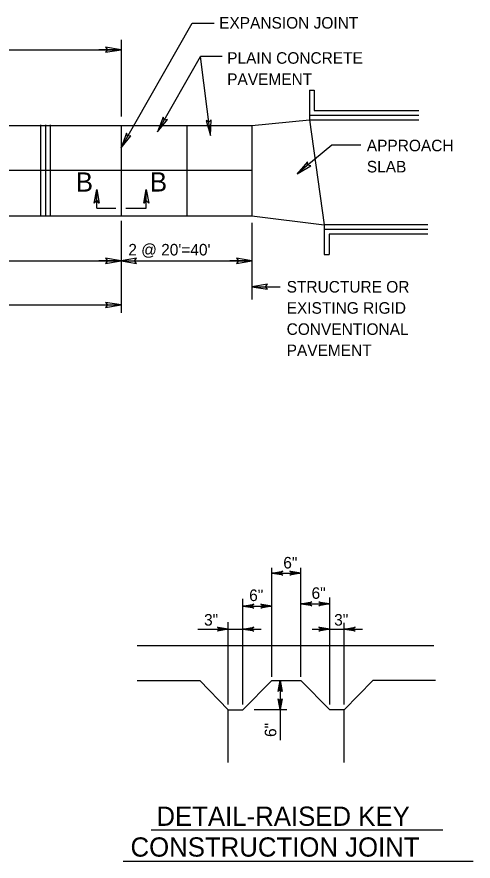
# Model space of a CAD drawing. Extents: x 3.1 to 10.2, y 1.2 to 11.3.
# Drawn here: x 6.918 to 9.286, y 6.773 to 11.16 of the extents above; entities that cross this region are included whole.
import ezdxf

# ---------------------------------------------------------------- set-up
doc = ezdxf.new("R2010")
doc.units = 0
for name, color, linetype in [('DETL-DIMS', 7, 'Continuous'), ('DETL-LINE', 7, 'Continuous'), ('DETL-NOTE', 7, 'Continuous'), ('DETL-TITL', 7, 'Continuous')]:
    doc.layers.add(name, color=color, linetype=linetype)

msp = doc.modelspace()

# ---------------------------------------------------------------- linework, layer by layer
at = {"layer": 'DETL-DIMS'}
for p, q in [((7.4583, 11.0402), (7.4583, 10.6414)), ((5.4958, 10.9893), (7.4583, 10.9893)), ((7.4583, 10.9893), (7.3436, 10.9893)), ((7.4583, 10.9893), (7.3785, 11.0026)), ((7.3785, 11.0026), (7.3886, 10.9893)), ((7.4583, 10.9893), (7.3785, 11.0026)), ((7.3785, 11.0026), (7.3886, 10.9893)), ((7.3886, 10.9893), (7.3786, 10.976)), ((7.3786, 10.976), (7.4583, 10.9893)), ((7.3886, 10.9893), (7.3786, 10.976)), ((7.3786, 10.976), (7.4583, 10.9893)), ((7.6486, 10.5634), (7.8712, 10.9542)), ((7.983, 10.9542), (7.8712, 10.9542)), ((7.9234, 10.5437), (7.8712, 10.9542)), ((7.6765, 10.6393), (7.6486, 10.5634)), ((7.6765, 10.6393), (7.6486, 10.5634)), ((7.6486, 10.5634), (7.6996, 10.6262)), ((7.6486, 10.5634), (7.6996, 10.6262)), ((7.6831, 10.624), (7.6765, 10.6393)), ((7.6831, 10.624), (7.6765, 10.6393)), ((7.6996, 10.6262), (7.6831, 10.624)), ((7.6996, 10.6262), (7.6831, 10.624)), ((7.9146, 10.6129), (7.9, 10.6212)), ((7.9, 10.6212), (7.9234, 10.5437)), ((7.9146, 10.6129), (7.9, 10.6212)), ((7.9, 10.6212), (7.9234, 10.5437)), ((7.9264, 10.6246), (7.9146, 10.6129)), ((7.9264, 10.6246), (7.9146, 10.6129)), ((7.9234, 10.5437), (7.9264, 10.6246)), ((7.9234, 10.5437), (7.9264, 10.6246)), ((7.4862, 10.5549), (7.4583, 10.479)), ((7.4862, 10.5549), (7.4583, 10.479)), ((7.4583, 10.479), (7.5093, 10.5418)), ((7.4583, 10.479), (7.5093, 10.5418)), ((7.4928, 10.5396), (7.4862, 10.5549)), ((7.4928, 10.5396), (7.4862, 10.5549)), ((7.5093, 10.5418), (7.4928, 10.5396)), ((7.5093, 10.5418), (7.4928, 10.5396)), ((8.4261, 10.4058), (8.3734, 10.3444)), ((8.4261, 10.4058), (8.3734, 10.3444)), ((8.427, 10.3891), (8.4261, 10.4058)), ((8.427, 10.3891), (8.4261, 10.4058)), ((8.3734, 10.3444), (8.4432, 10.3854)), ((8.3734, 10.3444), (8.4432, 10.3854)), ((8.4432, 10.3854), (8.427, 10.3891)), ((8.4432, 10.3854), (8.427, 10.3891)), ((7.3323, 10.2636), (7.3197, 10.1921)), ((7.3323, 10.1661), (7.3323, 10.2636)), ((7.3323, 10.2636), (7.3449, 10.1921)), ((7.5894, 10.2636), (7.5768, 10.1921)), ((7.5894, 10.1661), (7.5894, 10.2636)), ((7.5894, 10.2636), (7.602, 10.1921)), ((7.3197, 10.1921), (7.3323, 10.2056)), ((7.3323, 10.2056), (7.3449, 10.1921)), ((7.5768, 10.1921), (7.5894, 10.2056)), ((7.5894, 10.2056), (7.602, 10.1921)), ((7.3323, 10.1661), (7.431, 10.1661)), ((7.4827, 10.1661), (7.5894, 10.1661)), ((7.4583, 10.1008), (7.4583, 9.6211)), ((8.1382, 10.0903), (8.1382, 9.692)), ((5.7252, 9.8922), (7.4583, 9.8922)), ((7.4583, 9.8922), (7.3436, 9.8922)), ((7.4583, 9.8922), (7.3785, 9.9055)), ((7.3785, 9.9055), (7.3886, 9.8922)), ((7.4583, 9.8922), (7.3785, 9.9055)), ((7.3785, 9.9055), (7.3886, 9.8922)), ((7.3886, 9.8922), (7.3786, 9.8788)), ((7.3786, 9.8788), (7.4583, 9.8922)), ((7.3886, 9.8922), (7.3786, 9.8788)), ((7.3786, 9.8788), (7.4583, 9.8922)), ((7.5381, 9.9056), (7.4583, 9.8922)), ((7.5381, 9.9056), (7.4583, 9.8922)), ((7.4583, 9.8922), (8.1382, 9.8922)), ((7.4583, 9.8922), (7.5381, 9.879)), ((7.4583, 9.8922), (7.5381, 9.879)), ((7.4583, 9.8922), (7.605, 9.8922)), ((7.5281, 9.8922), (7.5381, 9.9056)), ((7.5281, 9.8922), (7.5381, 9.9056)), ((7.5381, 9.879), (7.5281, 9.8922)), ((7.5381, 9.879), (7.5281, 9.8922)), ((8.1382, 9.8922), (8.0235, 9.8922)), ((8.1382, 9.8922), (8.0584, 9.9055)), ((8.0584, 9.9055), (8.0685, 9.8922)), ((8.1382, 9.8922), (8.0584, 9.9055)), ((8.0584, 9.9055), (8.0685, 9.8922)), ((8.0685, 9.8922), (8.0585, 9.8788)), ((8.0585, 9.8788), (8.1382, 9.8922)), ((8.0685, 9.8922), (8.0585, 9.8788)), ((8.0585, 9.8788), (8.1382, 9.8922)), ((8.218, 9.7711), (8.1382, 9.7577)), ((8.218, 9.7711), (8.1382, 9.7577)), ((8.1382, 9.7577), (8.218, 9.7445)), ((8.1382, 9.7577), (8.218, 9.7445)), ((8.1382, 9.7577), (8.2849, 9.7577)), ((8.208, 9.7577), (8.218, 9.7711)), ((8.208, 9.7577), (8.218, 9.7711)), ((8.218, 9.7445), (8.208, 9.7577)), ((8.218, 9.7445), (8.208, 9.7577)), ((5.4958, 9.6628), (7.4583, 9.6628)), ((7.4583, 9.6628), (7.3785, 9.6761)), ((7.3785, 9.6761), (7.3886, 9.6628)), ((7.4583, 9.6628), (7.3785, 9.6761)), ((7.3785, 9.6761), (7.3886, 9.6628)), ((7.3886, 9.6628), (7.3786, 9.6494)), ((7.3786, 9.6494), (7.4583, 9.6628)), ((7.3886, 9.6628), (7.3786, 9.6494)), ((7.3786, 9.6494), (7.4583, 9.6628)), ((8.2412, 7.7307), (8.2412, 8.2962)), ((8.3918, 7.7307), (8.3918, 8.2962)), ((8.2412, 8.2693), (8.3918, 8.2693)), ((8.0908, 7.586), (8.0908, 8.1362)), ((8.5422, 7.586), (8.5422, 8.1419)), ((8.0908, 8.0982), (8.2412, 8.0982)), ((8.3918, 8.1096), (8.5422, 8.1096)), ((8.0155, 7.586), (8.0155, 8.0144)), ((8.6174, 7.586), (8.6174, 8.0106)), ((7.858, 7.9782), (8.1855, 7.9782)), ((8.4502, 7.9782), (8.7122, 7.9782)), ((8.2841, 7.7106), (8.2841, 7.4013)), ((8.1494, 7.56), (8.3188, 7.56))]:
    msp.add_line(p, q, dxfattribs=at)
for points in [[(7.4583, 10.479), (7.8275, 11.1271), (7.9422, 11.1271)], [(8.7036, 10.4935), (8.552, 10.4935), (8.3734, 10.3444)], [(8.2412, 8.2693), (8.2977, 8.2799), (8.2933, 8.2768), (8.2911, 8.2731), (8.2904, 8.2693), (8.2911, 8.2655), (8.2933, 8.2617), (8.2977, 8.2587), (8.2412, 8.2693), (8.2933, 8.2617), (8.2911, 8.2655), (8.2412, 8.2693), (8.2904, 8.2693), (8.2911, 8.2731), (8.2412, 8.2693), (8.2933, 8.2768)], [(8.3918, 8.2693), (8.3353, 8.2587), (8.3396, 8.2617), (8.3419, 8.2655), (8.3425, 8.2693), (8.3419, 8.2731), (8.3396, 8.2768), (8.3353, 8.2799), (8.3918, 8.2693), (8.3396, 8.2768), (8.3419, 8.2731), (8.3918, 8.2693), (8.3425, 8.2693), (8.3419, 8.2655), (8.3918, 8.2693), (8.3396, 8.2617)], [(8.3918, 8.1096), (8.4482, 8.1202), (8.4439, 8.1172), (8.4416, 8.1134), (8.441, 8.1096), (8.4416, 8.1058), (8.4439, 8.102), (8.4482, 8.099), (8.3918, 8.1096), (8.4439, 8.102), (8.4416, 8.1058), (8.3918, 8.1096), (8.441, 8.1096), (8.4416, 8.1134), (8.3918, 8.1096), (8.4439, 8.1172)], [(8.5422, 8.1096), (8.4857, 8.099), (8.49, 8.102), (8.4923, 8.1058), (8.4929, 8.1096), (8.4923, 8.1134), (8.49, 8.1172), (8.4857, 8.1202), (8.5422, 8.1096), (8.49, 8.1172), (8.4923, 8.1134), (8.5422, 8.1096), (8.4929, 8.1096), (8.4923, 8.1058), (8.5422, 8.1096), (8.49, 8.102)], [(8.0908, 8.0982), (8.1473, 8.1087), (8.1429, 8.1057), (8.1407, 8.1019), (8.14, 8.0982), (8.1407, 8.0944), (8.1429, 8.0906), (8.1473, 8.0876), (8.0908, 8.0982), (8.1429, 8.0906), (8.1407, 8.0944), (8.0908, 8.0982), (8.14, 8.0982), (8.1407, 8.1019), (8.0908, 8.0982), (8.1429, 8.1057)], [(8.2412, 8.0982), (8.1847, 8.0876), (8.189, 8.0906), (8.1913, 8.0944), (8.1919, 8.0982), (8.1913, 8.1019), (8.189, 8.1057), (8.1847, 8.1087), (8.2412, 8.0982), (8.189, 8.1057), (8.1913, 8.1019), (8.2412, 8.0982), (8.1919, 8.0982), (8.1913, 8.0944), (8.2412, 8.0982), (8.189, 8.0906)], [(8.0155, 7.9782), (7.959, 7.9676), (7.9633, 7.9706), (7.9656, 7.9744), (7.9662, 7.9782), (7.9656, 7.982), (7.9633, 7.9858), (7.959, 7.9888), (8.0155, 7.9782), (7.9633, 7.9858), (7.9656, 7.982), (8.0155, 7.9782), (7.9662, 7.9782), (7.9656, 7.9744), (8.0155, 7.9782), (7.9633, 7.9706)], [(8.0908, 7.9782), (8.1473, 7.9888), (8.1429, 7.9858), (8.1407, 7.982), (8.14, 7.9782), (8.1407, 7.9744), (8.1429, 7.9706), (8.1473, 7.9676), (8.0908, 7.9782), (8.1429, 7.9706), (8.1407, 7.9744), (8.0908, 7.9782), (8.14, 7.9782), (8.1407, 7.982), (8.0908, 7.9782), (8.1429, 7.9858)], [(8.5422, 7.9782), (8.4857, 7.9676), (8.49, 7.9706), (8.4923, 7.9744), (8.4929, 7.9782), (8.4923, 7.982), (8.49, 7.9858), (8.4857, 7.9888), (8.5422, 7.9782), (8.49, 7.9858), (8.4923, 7.982), (8.5422, 7.9782), (8.4929, 7.9782), (8.4923, 7.9744), (8.5422, 7.9782), (8.49, 7.9706)], [(8.6174, 7.9782), (8.6739, 7.9888), (8.6696, 7.9858), (8.6673, 7.982), (8.6667, 7.9782), (8.6673, 7.9744), (8.6696, 7.9706), (8.6739, 7.9676), (8.6174, 7.9782), (8.6696, 7.9706), (8.6673, 7.9744), (8.6174, 7.9782), (8.6667, 7.9782), (8.6673, 7.982), (8.6174, 7.9782), (8.6696, 7.9858)], [(8.2841, 7.7106), (8.2947, 7.6541), (8.2917, 7.6584), (8.2879, 7.6607), (8.2841, 7.6613), (8.2803, 7.6607), (8.2765, 7.6584), (8.2735, 7.6541), (8.2841, 7.7106), (8.2765, 7.6584), (8.2803, 7.6607), (8.2841, 7.7106), (8.2841, 7.6613), (8.2879, 7.6607), (8.2841, 7.7106), (8.2917, 7.6584)], [(8.2841, 7.56), (8.2735, 7.6165), (8.2765, 7.6122), (8.2803, 7.6099), (8.2841, 7.6093), (8.2879, 7.6099), (8.2917, 7.6122), (8.2947, 7.6165), (8.2841, 7.56), (8.2917, 7.6122), (8.2879, 7.6099), (8.2841, 7.56), (8.2841, 7.6093), (8.2803, 7.6099), (8.2841, 7.56), (8.2765, 7.6122)]]:
    msp.add_lwpolyline(points, dxfattribs=at)
for points in [[(7.3197, 10.1921), (7.3323, 10.2636), (7.3449, 10.1921), (7.3323, 10.2056)], [(7.5768, 10.1921), (7.5894, 10.2636), (7.602, 10.1921), (7.5894, 10.2056)]]:
    msp.add_lwpolyline(points, close=True, dxfattribs=at)
at = {"layer": 'DETL-LINE'}
for p, q in [((8.4365, 10.7786), (8.4615, 10.7786)), ((8.4615, 10.7786), (8.4615, 10.6742)), ((8.4615, 10.6742), (9.0037, 10.6742)), ((8.1382, 10.595), (8.4365, 10.6242)), ((8.4365, 10.6492), (9.0037, 10.6492)), ((8.4365, 10.6242), (8.5136, 10.0799)), ((4.9869, 10.595), (8.1382, 10.595)), ((7.0408, 10.5982), (7.0408, 10.1289)), ((7.0658, 10.5982), (7.0658, 10.1289)), ((7.0908, 10.5982), (7.0908, 10.1289)), ((7.4583, 10.595), (7.4583, 10.1258)), ((7.8004, 10.595), (7.8004, 10.1258)), ((8.1382, 10.595), (8.1382, 10.1258)), ((4.9869, 10.3635), (8.1382, 10.3635)), ((4.9869, 10.1258), (8.1382, 10.1258)), ((8.1382, 10.1258), (8.5136, 10.0799)), ((9.0517, 10.0799), (8.5136, 10.0799)), ((8.5136, 10.0799), (8.5136, 9.9256)), ((9.0517, 10.0549), (8.5136, 10.0549)), ((9.0517, 10.0299), (8.5386, 10.0299)), ((8.5386, 10.0299), (8.5386, 9.9256)), ((8.5136, 9.9256), (8.5386, 9.9256)), ((7.5422, 7.893), (9.0819, 7.893)), ((7.5422, 7.7106), (7.8667, 7.7106)), ((7.8667, 7.7106), (8.0155, 7.5588)), ((8.2412, 7.7106), (8.0908, 7.5588)), ((8.2412, 7.7106), (8.3918, 7.7106)), ((8.3918, 7.7106), (8.5422, 7.5588)), ((8.7662, 7.7106), (8.6174, 7.5588)), ((9.0907, 7.7106), (8.7662, 7.7106)), ((8.0155, 7.5588), (8.0908, 7.5588)), ((8.0155, 7.2845), (8.0155, 7.5588)), ((8.6174, 7.5588), (8.5422, 7.5588)), ((8.6174, 7.2845), (8.6174, 7.5588))]:
    msp.add_line(p, q, dxfattribs=at)
msp.add_lwpolyline([(8.4365, 10.7786), (8.4365, 10.6242), (9.0037, 10.6242)], dxfattribs=at)
at = {"layer": 'DETL-TITL'}
for p, q in [((7.6149, 6.935), (9.1297, 6.935)), ((7.47, 6.7726), (9.2863, 6.7726))]:
    msp.add_line(p, q, dxfattribs=at)

# ---------------------------------------------------------------- texts
at = {"layer": 'DETL-NOTE'}
for s, p in [('EXPANSION JOINT', (7.9678, 11.099)), ('PLAIN CONCRETE ', (8.0095, 10.9163)), ('PAVEMENT', (8.0095, 10.8063)), ('APPROACH ', (8.7345, 10.4615)), ('SLAB', (8.7345, 10.3515)), ("2 @ 20'=40'", (7.4962, 9.9201)), ('STRUCTURE OR ', (8.3183, 9.7273)), ('EXISTING RIGID', (8.3183, 9.6173)), ('CONVENTIONAL ', (8.3183, 9.5073)), ('PAVEMENT', (8.3183, 9.3973)), ('6"', (8.3009, 8.2934)), ('6"', (8.1238, 8.124)), ('6"', (8.4476, 8.1354)), ('3"', (7.8896, 7.9964)), ('3"', (8.5651, 7.9964))]:
    msp.add_text(s, height=0.06, dxfattribs=at).set_placement(p)
msp.add_text('6"', height=0.06, rotation=90, dxfattribs=at).set_placement((8.2646, 7.4177))
at = {"layer": 'DETL-TITL'}
for s, p in [('B', (7.2237, 10.2519)), ('B', (7.6084, 10.2524)), ('DETAIL-RAISED KEY', (7.6422, 6.9559)), ('CONSTRUCTION JOINT', (7.5077, 6.7959))]:
    msp.add_text(s, height=0.1, dxfattribs=at).set_placement(p)

doc.saveas('drawing.dxf')
